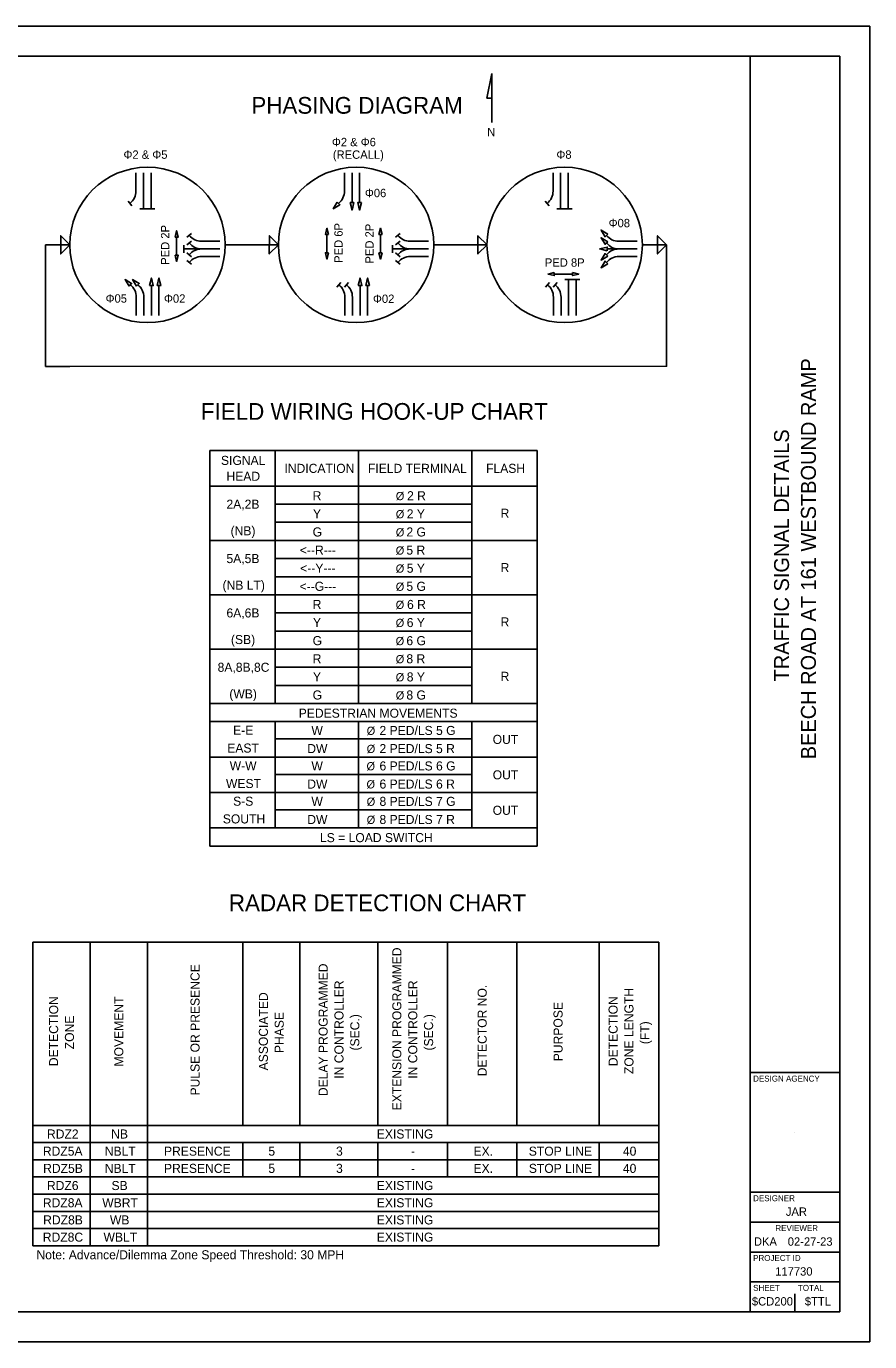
# Model space of a CAD drawing. Extents: x 0 to 34, y 0 to 22.
# Drawn here: x 19.89 to 34, y 0 to 22 of the extents above; entities that cross this region are included whole.
import ezdxf

# ---------------------------------------------------------------- set-up
doc = ezdxf.new("R2010")
doc.units = 0
for name, color, linetype in [('SG_P_Text', 7, 'Continuous'), ('SH_Border', 7, 'Continuous'), ('SH_Cut_Line', 7, 'Continuous'), ('SH_Data', 7, 'Continuous'), ('SH_Text', 7, 'Continuous')]:
    doc.layers.add(name, color=color, linetype=linetype)

msp = doc.modelspace()

# ---------------------------------------------------------------- linework, layer by layer
at = {"layer": 'SG_P_Text'}
for p, q in [((21.724, 19.549), (21.724, 19.244)), ((21.851, 19.549), (21.851, 18.949)), ((21.977, 19.549), (21.977, 18.949)), ((25.214, 19.549), (25.214, 19.244)), ((25.34, 19.051), (25.34, 19.549)), ((25.467, 19.051), (25.467, 19.549)), ((28.703, 19.549), (28.703, 19.244)), ((28.83, 19.549), (28.83, 18.949)), ((28.957, 19.549), (28.957, 18.949)), ((21.657, 18.997), (21.593, 19.077)), ((21.914, 18.949), (21.787, 18.949)), ((22.041, 18.949), (21.914, 18.949)), ((28.636, 18.997), (28.572, 19.077)), ((28.893, 18.949), (28.767, 18.949)), ((29.02, 18.949), (28.893, 18.949)), ((22.577, 18.471), (22.656, 18.535)), ((24.92, 18.213), (24.92, 18.518)), ((25.815, 18.213), (25.815, 18.518)), ((26.066, 18.471), (26.146, 18.535)), ((22.405, 18.476), (22.405, 18.171)), ((22.528, 18.213), (22.528, 18.34)), ((23.129, 18.277), (22.528, 18.277)), ((22.577, 18.344), (22.656, 18.408)), ((23.129, 18.404), (22.823, 18.404)), ((23.129, 18.277), (22.823, 18.277)), ((23.129, 18.277), (22.823, 18.277)), ((24.108, 18.344), (23.218, 18.344)), ((26.018, 18.213), (26.018, 18.34)), ((26.618, 18.277), (26.018, 18.277)), ((26.066, 18.344), (26.146, 18.408)), ((26.618, 18.404), (26.313, 18.404)), ((26.618, 18.277), (26.313, 18.277)), ((26.618, 18.277), (26.313, 18.277)), ((27.598, 18.344), (26.707, 18.344)), ((29.61, 18.277), (30.108, 18.277)), ((30.108, 18.404), (29.803, 18.404)), ((30.108, 18.277), (29.803, 18.277)), ((30.108, 18.277), (29.803, 18.277)), ((22.577, 18.21), (22.656, 18.146)), ((22.577, 18.083), (22.656, 18.019)), ((23.129, 18.15), (22.823, 18.15)), ((26.066, 18.21), (26.146, 18.146)), ((26.066, 18.083), (26.146, 18.019)), ((26.618, 18.15), (26.313, 18.15)), ((30.108, 18.15), (29.803, 18.15)), ((29.029, 17.857), (28.724, 17.857)), ((21.983, 17.663), (21.983, 17.165)), ((22.11, 17.663), (22.11, 17.165)), ((25.152, 17.717), (25.088, 17.637)), ((25.279, 17.717), (25.215, 17.637)), ((25.473, 17.663), (25.473, 17.165)), ((25.6, 17.663), (25.6, 17.165)), ((28.642, 17.717), (28.578, 17.637)), ((28.769, 17.717), (28.705, 17.637)), ((28.899, 17.765), (29.026, 17.765)), ((28.963, 17.165), (28.963, 17.765)), ((29.026, 17.765), (29.153, 17.765)), ((29.089, 17.165), (29.089, 17.765)), ((21.73, 17.165), (21.73, 17.47)), ((21.856, 17.165), (21.856, 17.47)), ((25.219, 17.165), (25.219, 17.47)), ((25.346, 17.165), (25.346, 17.47)), ((28.709, 17.165), (28.709, 17.47)), ((28.836, 17.165), (28.836, 17.47))]:
    msp.add_line(p, q, dxfattribs=at)
for points in [[(25.093, 19.059), (25.026, 18.949), (25.137, 19.015)], [(25.372, 19.051), (25.34, 18.926), (25.309, 19.051)], [(25.498, 19.051), (25.467, 18.926), (25.436, 19.051)], [(20.618, 18.344), (20.467, 18.496), (20.467, 18.193)], [(22.379, 18.476), (22.405, 18.58), (22.431, 18.476)], [(24.108, 18.344), (23.957, 18.496), (23.956, 18.193)], [(24.946, 18.518), (24.92, 18.622), (24.894, 18.518)], [(25.841, 18.518), (25.815, 18.622), (25.789, 18.518)], [(27.598, 18.344), (27.446, 18.496), (27.446, 18.193)], [(29.618, 18.525), (29.507, 18.591), (29.574, 18.48)], [(30.603, 18.344), (30.452, 18.496), (30.452, 18.193)], [(29.61, 18.246), (29.485, 18.277), (29.61, 18.308)], [(29.618, 18.398), (29.507, 18.464), (29.574, 18.354)], [(22.379, 18.171), (22.405, 18.067), (22.431, 18.171)], [(24.946, 18.213), (24.92, 18.108), (24.894, 18.213)], [(25.841, 18.213), (25.815, 18.108), (25.789, 18.213)], [(29.618, 18.156), (29.507, 18.09), (29.574, 18.2)], [(29.618, 18.029), (29.507, 17.963), (29.574, 18.073)], [(28.724, 17.883), (28.62, 17.857), (28.724, 17.831)], [(29.029, 17.883), (29.133, 17.857), (29.029, 17.831)], [(21.609, 17.655), (21.542, 17.765), (21.653, 17.699)], [(21.735, 17.655), (21.669, 17.765), (21.78, 17.699)], [(21.952, 17.663), (21.983, 17.788), (22.015, 17.663)], [(22.079, 17.663), (22.11, 17.788), (22.141, 17.663)], [(25.442, 17.663), (25.473, 17.788), (25.504, 17.663)], [(25.569, 17.663), (25.6, 17.788), (25.631, 17.663)]]:
    msp.add_lwpolyline(points, close=True, dxfattribs=at)
msp.add_lwpolyline([(30.197, 18.344), (30.603, 18.344), (30.603, 16.314), (20.618, 16.313), (20.212, 16.313), (20.212, 18.344), (20.618, 18.344)], dxfattribs=at)
for centre in [(21.918, 18.344), (25.408, 18.344), (28.897, 18.344)]:
    msp.add_circle(centre, 1.3, dxfattribs=at)
for centre, start, end in [((21.459, 19.244), 308.7993, 0), ((24.949, 19.244), 308.8122, 0.0129), ((28.438, 19.244), 308.7993, 0), ((22.823, 18.669), 218.7993, 270), ((26.313, 18.669), 218.7993, 270), ((29.803, 18.669), 218.7993, 270), ((22.823, 18.542), 218.7993, 270), ((22.823, 18.012), 90, 141.2007), ((26.313, 18.542), 218.7993, 270), ((26.313, 18.012), 90, 141.2007), ((29.803, 18.542), 218.7864, 269.9871), ((29.803, 18.012), 90, 141.2007), ((22.823, 17.885), 90, 141.2007), ((26.313, 17.885), 90, 141.2007), ((29.803, 17.885), 90, 141.2007), ((21.465, 17.47), 360, 51.2007), ((21.591, 17.47), 360, 51.2007), ((24.954, 17.47), 360, 51.2007), ((25.081, 17.47), 360, 51.2007), ((28.444, 17.47), 360, 51.2007), ((28.571, 17.47), 360, 51.2007)]:
    msp.add_arc(centre, 0.265, start, end, dxfattribs=at)
at = {"layer": 'SH_Border'}
for p, q in [((32, 0.5), (32, 21.5)), ((32, 4.5), (33.5, 4.5)), ((32, 2.5), (33.5, 2.5)), ((32, 2), (33.5, 2)), ((32, 1.5), (33.5, 1.5)), ((32, 1), (33.5, 1))]:
    msp.add_line(p, q, dxfattribs=at)
msp.add_lwpolyline([(1.5, 21.5), (33.5, 21.5), (33.5, 0.5), (1.5, 0.5)], close=True, dxfattribs=at)
at = {"layer": 'SH_Cut_Line'}
msp.add_lwpolyline([(0, 0), (34, 0), (34, 22), (0, 22)], close=True, dxfattribs=at)
at = {"layer": 'SH_Data'}
for p, q in [((32.75, 3.5), (32.75, 3.5)), ((32.375, 0.675), (32.375, 0.675)), ((32.75, 0.5), (32.75, 0.8))]:
    msp.add_line(p, q, dxfattribs=at)
at = {"layer": 'SH_Text'}
for p, q in [((27.677, 20.389), (27.677, 21.209)), ((22.958, 14.903), (28.439, 14.903)), ((22.958, 14.903), (22.958, 14.007)), ((24.051, 14.903), (24.051, 14.007)), ((25.448, 14.903), (25.448, 14.007)), ((27.345, 14.903), (27.345, 14.007)), ((28.439, 14.903), (28.439, 14.007)), ((22.958, 14.31), (28.439, 14.31)), ((22.958, 14.007), (22.958, 13.401)), ((24.051, 14.007), (27.345, 14.007)), ((24.051, 14.007), (24.051, 13.401)), ((25.448, 14.007), (25.448, 13.401)), ((27.345, 14.007), (27.345, 13.401)), ((28.439, 14.007), (28.439, 13.401)), ((24.051, 13.704), (27.345, 13.704)), ((22.958, 13.401), (28.439, 13.401)), ((22.958, 13.401), (22.958, 11.886)), ((24.051, 13.401), (24.051, 11.886)), ((25.448, 13.401), (25.448, 11.886)), ((27.345, 13.401), (27.345, 11.886)), ((28.439, 13.401), (28.439, 11.886)), ((24.051, 13.098), (27.345, 13.098)), ((24.051, 12.795), (27.345, 12.795)), ((22.958, 12.492), (28.439, 12.492)), ((24.051, 12.189), (27.345, 12.189)), ((22.958, 11.886), (22.958, 11.583)), ((24.051, 11.886), (27.345, 11.886)), ((24.051, 11.886), (24.051, 11.583)), ((25.448, 11.886), (25.448, 11.583)), ((27.345, 11.886), (27.345, 11.583)), ((28.439, 11.886), (28.439, 11.583)), ((22.958, 11.583), (28.439, 11.583)), ((22.958, 11.583), (22.958, 11.28)), ((24.051, 11.583), (24.051, 11.28)), ((25.448, 11.583), (25.448, 11.28)), ((27.345, 11.583), (27.345, 11.28)), ((28.439, 11.583), (28.439, 11.28)), ((22.958, 11.28), (22.958, 10.674)), ((24.051, 11.28), (27.345, 11.28)), ((24.051, 11.28), (24.051, 10.674)), ((25.448, 11.28), (25.448, 10.674)), ((27.345, 11.28), (27.345, 10.674)), ((28.439, 11.28), (28.439, 10.674)), ((24.051, 10.977), (27.345, 10.977)), ((22.958, 10.674), (28.439, 10.674)), ((22.958, 10.674), (22.958, 9.488)), ((28.439, 10.674), (28.439, 9.488)), ((22.958, 10.371), (28.439, 10.371)), ((24.051, 10.371), (24.051, 9.488)), ((25.448, 10.371), (25.448, 9.488)), ((27.345, 10.371), (27.345, 9.488)), ((24.051, 10.081), (27.345, 10.081)), ((22.958, 9.778), (28.439, 9.778)), ((22.958, 9.488), (22.958, 9.185)), ((24.051, 9.488), (27.345, 9.488)), ((24.051, 9.488), (24.051, 9.185)), ((25.448, 9.488), (25.448, 9.185)), ((27.345, 9.488), (27.345, 9.185)), ((28.439, 9.488), (28.439, 9.185)), ((22.958, 9.185), (28.439, 9.185)), ((22.958, 9.185), (22.958, 8.895)), ((24.051, 9.185), (24.051, 8.895)), ((25.448, 9.185), (25.448, 8.895)), ((27.345, 9.185), (27.345, 8.895)), ((28.439, 9.185), (28.439, 8.895)), ((22.958, 8.895), (22.958, 8.592)), ((24.051, 8.895), (27.345, 8.895)), ((24.051, 8.895), (24.051, 8.592)), ((25.448, 8.895), (25.448, 8.592)), ((27.345, 8.895), (27.345, 8.592)), ((28.439, 8.895), (28.439, 8.592)), ((22.958, 8.592), (28.439, 8.592)), ((22.958, 8.592), (22.958, 8.289)), ((28.439, 8.592), (28.439, 8.289)), ((22.958, 8.289), (28.439, 8.289)), ((20, 6.684), (25.774, 6.684)), ((20, 6.684), (20, 2.755)), ((20.959, 6.684), (20.959, 2.755)), ((21.917, 6.684), (21.917, 2.755)), ((23.51, 6.684), (23.51, 3.618)), ((24.468, 6.684), (24.468, 3.618)), ((25.774, 6.684), (28.098, 6.684)), ((25.774, 6.684), (25.774, 3.618)), ((26.936, 6.684), (26.936, 3.618)), ((28.098, 6.684), (30.47, 6.684)), ((28.098, 6.684), (28.098, 3.618)), ((29.475, 6.684), (29.475, 3.618)), ((30.47, 6.684), (30.47, 2.755)), ((20, 3.618), (25.774, 3.618)), ((25.774, 3.618), (28.098, 3.618)), ((28.098, 3.618), (30.47, 3.618)), ((20, 3.33), (25.774, 3.33)), ((23.51, 3.33), (23.51, 2.755)), ((24.468, 3.33), (24.468, 2.755)), ((25.774, 3.33), (28.098, 3.33)), ((25.774, 3.33), (25.774, 2.755)), ((26.936, 3.33), (26.936, 2.755)), ((28.098, 3.33), (30.47, 3.33)), ((28.098, 3.33), (28.098, 2.755)), ((29.475, 3.33), (29.475, 2.755)), ((20, 3.043), (25.774, 3.043)), ((25.774, 3.043), (28.098, 3.043)), ((28.098, 3.043), (30.47, 3.043)), ((20, 2.755), (25.774, 2.755)), ((20, 2.755), (20, 1.893)), ((20.959, 2.755), (20.959, 1.893)), ((21.917, 2.755), (21.917, 1.893)), ((25.774, 2.755), (28.098, 2.755)), ((28.098, 2.755), (30.47, 2.755)), ((30.47, 2.755), (30.47, 1.893)), ((20, 2.468), (25.774, 2.468)), ((25.774, 2.468), (28.098, 2.468)), ((28.098, 2.468), (30.47, 2.468)), ((20, 2.18), (25.774, 2.18)), ((25.774, 2.18), (28.098, 2.18)), ((28.098, 2.18), (30.47, 2.18)), ((20, 1.893), (25.774, 1.893)), ((20, 1.893), (20, 1.605)), ((20.959, 1.893), (20.959, 1.605)), ((21.917, 1.893), (21.917, 1.605)), ((25.774, 1.893), (28.098, 1.893)), ((28.098, 1.893), (30.47, 1.893)), ((30.47, 1.893), (30.47, 1.605)), ((20, 1.605), (25.774, 1.605)), ((25.774, 1.605), (28.098, 1.605)), ((28.098, 1.605), (30.47, 1.605))]:
    msp.add_line(p, q, dxfattribs=at)
msp.add_lwpolyline([(27.677, 21.209), (27.595, 20.799), (27.677, 20.799)], close=True, dxfattribs=at)

# ---------------------------------------------------------------- texts
at = {"layer": 'SG_P_Text'}
for s, height, p in [('PHASING DIAGRAM', 0.28, (23.655, 20.538)), ('Φ2 & Φ6', 0.14, (25.003, 19.994)), ('Φ2 & Φ5', 0.14, (21.516, 19.784)), ('(RECALL)', 0.14, (25.019, 19.784)), ('Φ8', 0.14, (28.759, 19.784)), ('Φ06', 0.14, (25.555, 19.142)), ('Φ08', 0.14, (29.633, 18.639)), ('Φ05', 0.14, (21.217, 17.378)), ('Φ02', 0.14, (22.194, 17.377)), ('Φ02', 0.14, (25.69, 17.373)), ('FIELD WIRING HOOK-UP CHART', 0.28, (22.811, 15.419)), ('RADAR DETECTION CHART', 0.28, (23.279, 7.2))]:
    msp.add_text(s, height=height, dxfattribs=at).set_placement(p)
for s, rotation, p in [('PED 2P', 90, (22.283, 18.011)), ('PED 6P', 90, (25.183, 18.044)), ('PED 2P', 90, (25.701, 18.032)), ('PED 8P', 360, (28.565, 17.979))]:
    msp.add_text(s, height=0.14, rotation=rotation, dxfattribs=at).set_placement(p)
at = {"layer": 'SH_Data'}
for s, p in [('BEECH ROAD AT 161 WESTBOUND RAMP', (33.1, 9.741)), ('TRAFFIC SIGNAL DETAILS', (32.65, 11.043))]:
    msp.add_text(s, height=0.25, rotation=90, dxfattribs=at).set_placement(p)
for s, height, p in [('DESIGN AGENCY', 0.1, (32.05, 4.35)), ('DESIGNER', 0.1, (32.05, 2.35)), ('JAR', 0.14, (32.597, 2.105)), ('REVIEWER', 0.1, (32.422, 1.85)), ('DKA', 0.14, (32.063, 1.605)), ('02-27-23', 0.14, (32.629, 1.605)), ('PROJECT ID', 0.1, (32.05, 1.35)), ('117730', 0.14, (32.419, 1.105)), ('SHEET', 0.1, (32.05, 0.85)), ('TOTAL', 0.1, (32.8, 0.85)), ('$CD200', 0.14, (32.029, 0.605)), ('$TTL', 0.14, (32.915, 0.605))]:
    msp.add_text(s, height=height, dxfattribs=at).set_placement(p)
at = {"layer": 'SH_Text'}
for s, height, p in [('N', 0.14, (27.601, 20.161)), ('SIGNAL ', 0.1515, (23.147, 14.664)), ('HEAD', 0.1515, (23.239, 14.398)), ('INDICATION', 0.1515, (24.209, 14.531)), ('FIELD TERMINAL', 0.15153, (25.606, 14.531)), ('FLASH', 0.1515, (27.582, 14.531)), ('2A,2B', 0.1515, (23.239, 13.932)), ('R', 0.152, (24.681, 14.073)), ('Ø', 0.137, (26.072, 14.075)), ('2 R', 0.1515, (26.26, 14.073)), ('Y', 0.152, (24.686, 13.77)), ('Ø', 0.137, (26.072, 13.771)), ('2 Y', 0.1515, (26.255, 13.77)), ('R', 0.152, (27.824, 13.78)), ('(NB)', 0.1515, (23.308, 13.487)), ('G', 0.152, (24.681, 13.467)), ('Ø', 0.137, (26.072, 13.468)), ('2 G', 0.1515, (26.249, 13.467)), ('<--R---', 0.1515, (24.467, 13.164)), ('Ø', 0.137, (26.071, 13.165)), ('5 R', 0.1515, (26.249, 13.164)), ('5A,5B', 0.1515, (23.239, 13.022)), ('<--Y---', 0.1515, (24.473, 12.861)), ('Ø', 0.137, (26.071, 12.862)), ('5 Y', 0.1515, (26.255, 12.861)), ('R', 0.152, (27.824, 12.871)), ('(NB LT)', 0.1515, (23.173, 12.578)), ('<--G---', 0.1515, (24.462, 12.558)), ('Ø', 0.137, (26.071, 12.559)), ('5 G', 0.1515, (26.249, 12.558)), ('R', 0.152, (24.681, 12.255)), ('Ø', 0.137, (26.07, 12.256)), ('6 R', 0.1515, (26.26, 12.255)), ('6A,6B', 0.1515, (23.239, 12.113)), ('Y', 0.152, (24.686, 11.952)), ('6 Y', 0.1515, (26.255, 11.952)), ('R', 0.152, (27.824, 11.962)), ('Ø', 0.137, (26.07, 11.953)), ('(SB)', 0.1515, (23.314, 11.668)), ('G', 0.152, (24.681, 11.649)), ('Ø', 0.137, (26.07, 11.65)), ('6 G', 0.1515, (26.249, 11.649)), ('R', 0.152, (24.681, 11.346)), ('Ø', 0.137, (26.071, 11.347)), ('8 R', 0.1515, (26.249, 11.346)), ('8A,8B,8C', 0.1515, (23.091, 11.204)), ('Y', 0.152, (24.686, 11.043)), ('Ø', 0.137, (26.071, 11.044)), ('8 Y', 0.1515, (26.255, 11.043)), ('R', 0.152, (27.824, 11.052)), ('(WB)', 0.1515, (23.287, 10.759)), ('G', 0.152, (24.681, 10.74)), ('Ø', 0.137, (26.071, 10.741)), ('8 G', 0.1515, (26.249, 10.74)), ('PEDESTRIAN MOVEMENTS', 0.15153, (24.448, 10.436)), ('E-E', 0.1515, (23.35, 10.15)), ('W', 0.152, (24.66, 10.147)), ('Ø', 0.137, (25.585, 10.149)), ('2 PED/LS 5 G', 0.15153, (25.799, 10.147)), ('OUT', 0.1515, (27.693, 9.998)), ('EAST', 0.1515, (23.252, 9.853)), ('DW', 0.1515, (24.591, 9.844)), ('Ø', 0.137, (25.585, 9.846)), ('2 PED/LS 5 R', 0.15153, (25.799, 9.844)), ('W-W', 0.1515, (23.293, 9.557)), ('W', 0.152, (24.66, 9.554)), ('Ø', 0.137, (25.582, 9.556)), ('6 PED/LS 6 G', 0.15153, (25.799, 9.554)), ('OUT', 0.1515, (27.693, 9.405)), ('WEST', 0.1515, (23.231, 9.26)), ('DW', 0.1515, (24.591, 9.251)), ('Ø', 0.137, (25.582, 9.253)), ('6 PED/LS 6 R', 0.15153, (25.799, 9.251)), ('S-S', 0.1515, (23.35, 8.964)), ('W', 0.152, (24.66, 8.961)), ('Ø', 0.137, (25.585, 8.963)), ('8 PED/LS 7 G', 0.15153, (25.799, 8.961)), ('SOUTH', 0.1515, (23.178, 8.668)), ('DW', 0.1515, (24.591, 8.658)), ('Ø', 0.137, (25.585, 8.66)), ('8 PED/LS 7 R', 0.15153, (25.799, 8.658)), ('OUT', 0.1515, (27.693, 8.812)), ('LS = LOAD SWITCH', 0.15153, (24.803, 8.355)), ('RDZ2', 0.1515, (20.236, 3.398)), ('NB', 0.1515, (21.31, 3.398)), ('EXISTING', 0.1515, (25.754, 3.398)), ('RDZ5A', 0.1515, (20.167, 3.111)), ('NBLT', 0.1515, (21.203, 3.111)), ('PRESENCE', 0.1515, (22.194, 3.111)), ('5', 0.152, (23.94, 3.111)), ('3', 0.152, (25.072, 3.111)), ('-', 0.152, (26.326, 3.111)), ('EX.', 0.1515, (27.372, 3.111)), ('STOP LINE', 0.1515, (28.297, 3.111)), ('40', 0.1515, (29.871, 3.111)), ('RDZ5B', 0.1515, (20.172, 2.823)), ('NBLT', 0.1515, (21.203, 2.823)), ('PRESENCE', 0.1515, (22.194, 2.823)), ('5', 0.152, (23.94, 2.823)), ('3', 0.152, (25.072, 2.823)), ('-', 0.152, (26.326, 2.823)), ('EX.', 0.1515, (27.372, 2.823)), ('STOP LINE', 0.1515, (28.297, 2.823)), ('40', 0.1515, (29.871, 2.823)), ('RDZ6', 0.1515, (20.235, 2.536)), ('SB', 0.1515, (21.316, 2.536)), ('EXISTING', 0.1515, (25.754, 2.536)), ('RDZ8A', 0.1515, (20.167, 2.248)), ('WBRT', 0.1515, (21.161, 2.248)), ('EXISTING', 0.1515, (25.754, 2.248)), ('RDZ8B', 0.1515, (20.172, 1.961)), ('WB', 0.1515, (21.289, 1.961)), ('EXISTING', 0.1515, (25.754, 1.961)), ('RDZ8C', 0.1515, (20.166, 1.673)), ('WBLT', 0.1515, (21.182, 1.673)), ('EXISTING', 0.1515, (25.754, 1.673)), ('Note: Advance/Dilemma Zone Speed Threshold: 30 MPH', 0.15153, (20.06, 1.378))]:
    msp.add_text(s, height=height, dxfattribs=at).set_placement(p)
for s, height, p in [('EXTENSION PROGRAMMED', 0.15153, (26.165, 3.869)), ('PULSE OR PRESENCE', 0.15153, (22.789, 4.118)), ('DELAY PROGRAMMED', 0.15153, (24.932, 4.107)), (' IN CONTROLLER', 0.15153, (25.197, 4.342)), (' IN CONTROLLER', 0.15153, (26.431, 4.342)), ('DETECTOR NO.', 0.15153, (27.593, 4.439)), ('DETECTION', 0.1515, (20.423, 4.608)), ('MOVEMENT', 0.1515, (21.513, 4.602)), ('ASSOCIATED', 0.1515, (23.932, 4.538)), ('DETECTION', 0.1515, (29.783, 4.608)), ('ZONE LENGTH', 0.15153, (30.048, 4.476)), ('PHASE', 0.1515, (24.197, 4.827)), ('PURPOSE', 0.1515, (28.862, 4.69)), ('ZONE', 0.1515, (20.688, 4.891)), ('(SEC.)', 0.1515, (25.462, 4.87)), ('(SEC.)', 0.1515, (26.696, 4.87)), ('(FT)', 0.1515, (30.313, 4.976))]:
    msp.add_text(s, height=height, rotation=90, dxfattribs=at).set_placement(p)

doc.saveas('drawing.dxf')
